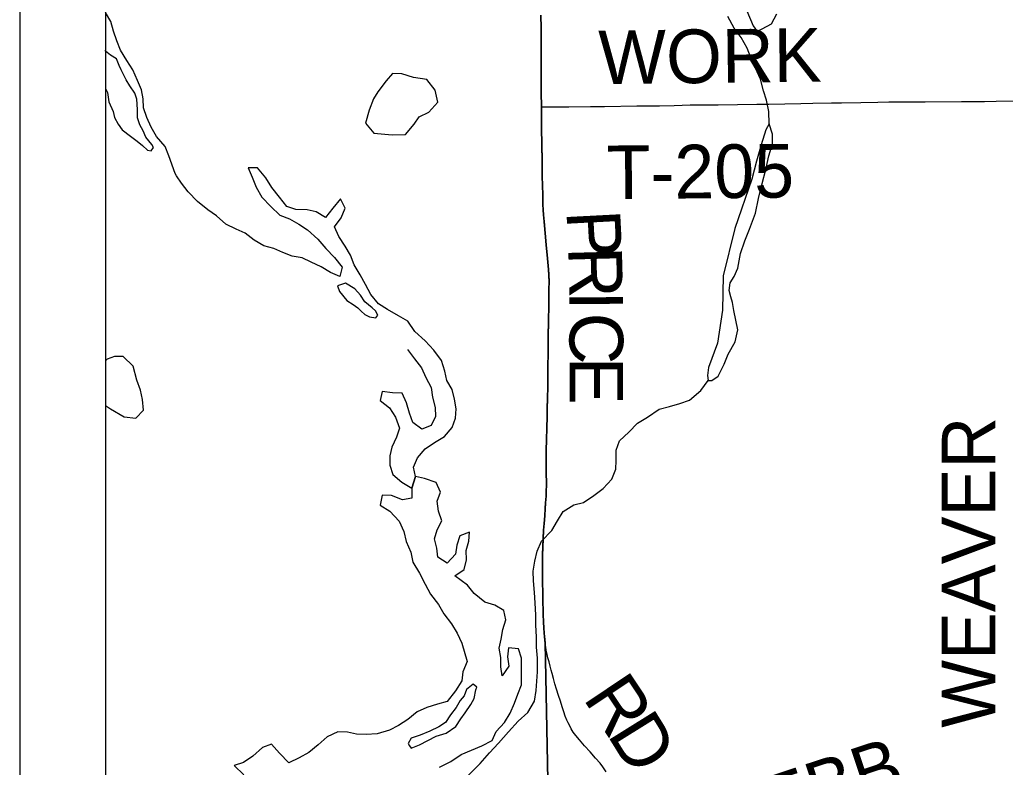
# Model space of a CAD drawing. Extents: x 0 to 34, y 0 to 22.
# Drawn here: x 12.556 to 13.6, y 13.505 to 14.297 of the extents above; entities that cross this region are included whole.
import ezdxf

# ---------------------------------------------------------------- set-up
doc = ezdxf.new("R2010")
doc.units = 0
for name, color, linetype in [('GM_X_Corporation', 7, 'Continuous'), ('GM_X_County_Road_Text', 7, 'Continuous'), ('GM_X_Major_Lake', 7, 'Continuous'), ('GM_X_Major_River', 7, 'Continuous'), ('GM_X_Minor_Lake', 7, 'Continuous'), ('GM_X_Minor_River', 7, 'Continuous'), ('GM_X_Township_Road', 7, 'Continuous'), ('GM_X_Township_Road_Text', 7, 'Continuous'), ('SH_Data', 7, 'Continuous')]:
    doc.layers.add(name, color=color, linetype=linetype)

msp = doc.modelspace()

# ---------------------------------------------------------------- linework, layer by layer
at = {"layer": 'GM_X_Corporation'}
for points in [[(12.6467, 16.7214), (12.6467, 12.6578)], [(12.6467, 16.7214), (12.6467, 12.6578)], [(13.1224, 13.1277), (13.1125, 13.6369), (13.1121, 13.6402), (13.1118, 13.6437), (13.1116, 13.6469), (13.1112, 13.6528), (13.1109, 13.6587), (13.1105, 13.6672), (13.1104, 13.6719), (13.1102, 13.6796), (13.1101, 13.686), (13.11, 13.6925), (13.1099, 13.6984), (13.1098, 13.7049), (13.1099, 13.7101), (13.1099, 13.7182), (13.1099, 13.73), (13.1102, 13.7387), (13.1106, 13.7476), (13.111, 13.756), (13.1115, 13.7632), (13.1121, 13.7714), (13.1127, 13.7791), (13.1131, 13.7852), (13.1136, 13.7923), (13.1138, 13.7982), (13.1139, 13.803), (13.1139, 13.8088), (13.1138, 13.814), (13.1137, 13.8196), (13.1136, 13.8235), (13.1136, 13.8295), (13.1136, 13.8333), (13.1137, 13.8414), (13.114, 13.8512), (13.1144, 13.8651), (13.1146, 13.8754), (13.1148, 13.885), (13.1151, 13.8963), (13.1153, 13.9075), (13.1155, 13.9187), (13.1156, 13.929), (13.1157, 13.944), (13.1158, 13.958), (13.1162, 13.9811), (13.1164, 13.9909), (13.1166, 14.0047), (13.1166, 14.0115), (13.1167, 14.0191), (13.1164, 14.0268), (13.1161, 14.0323), (13.1151, 14.0439), (13.1138, 14.0585), (13.1114, 14.0829), (13.1109, 14.0901), (13.1105, 14.0954), (13.1103, 14.101), (13.11, 14.1119), (13.1098, 14.1203), (13.1095, 14.1318), (13.1093, 14.1464), (13.109, 14.1658), (13.1089, 14.1808), (13.1087, 14.2049), (13.1085, 14.2194), (13.1084, 14.2355), (13.1083, 14.2594), (13.1083, 14.2707), (13.1082, 14.2879), (13.1081, 14.3017)], [(13.1224, 13.1277), (13.1125, 13.6369), (13.1121, 13.6402), (13.1118, 13.6437), (13.1116, 13.6469), (13.1112, 13.6528), (13.1109, 13.6587), (13.1105, 13.6672), (13.1104, 13.6719), (13.1102, 13.6796), (13.1101, 13.686), (13.11, 13.6925), (13.1099, 13.6984), (13.1098, 13.7049), (13.1099, 13.7101), (13.1099, 13.7182), (13.1099, 13.73), (13.1102, 13.7387), (13.1106, 13.7476), (13.111, 13.756), (13.1115, 13.7632), (13.1121, 13.7714), (13.1127, 13.7791), (13.1131, 13.7852), (13.1136, 13.7923), (13.1138, 13.7982), (13.1139, 13.803), (13.1139, 13.8088), (13.1138, 13.814), (13.1137, 13.8196), (13.1136, 13.8235), (13.1136, 13.8295), (13.1136, 13.8333), (13.1137, 13.8414), (13.114, 13.8512), (13.1144, 13.8651), (13.1146, 13.8754), (13.1148, 13.885), (13.1151, 13.8963), (13.1153, 13.9075), (13.1155, 13.9187), (13.1156, 13.929), (13.1157, 13.944), (13.1158, 13.958), (13.1162, 13.9811), (13.1164, 13.9909), (13.1166, 14.0047), (13.1166, 14.0115), (13.1167, 14.0191), (13.1164, 14.0268), (13.1161, 14.0323), (13.1151, 14.0439), (13.1138, 14.0585), (13.1114, 14.0829), (13.1109, 14.0901), (13.1105, 14.0954), (13.1103, 14.101), (13.11, 14.1119), (13.1098, 14.1203), (13.1095, 14.1318), (13.1093, 14.1464), (13.109, 14.1658), (13.1089, 14.1808), (13.1087, 14.2049), (13.1085, 14.2194), (13.1084, 14.2355), (13.1083, 14.2594), (13.1083, 14.2707), (13.1082, 14.2879), (13.1081, 14.3017)], [(13.1081, 14.3017), (13.1082, 14.2879), (13.1083, 14.2707), (13.1083, 14.2594), (13.1084, 14.2355), (13.1085, 14.2194), (13.1087, 14.2049), (13.1089, 14.1808), (13.109, 14.1658), (13.1093, 14.1464), (13.1095, 14.1318), (13.1098, 14.1203), (13.11, 14.1119), (13.1103, 14.101), (13.1105, 14.0954), (13.1109, 14.0901), (13.1114, 14.0829), (13.1138, 14.0585), (13.1151, 14.0439), (13.1161, 14.0323), (13.1164, 14.0268), (13.1167, 14.0191), (13.1166, 14.0115), (13.1166, 14.0047), (13.1164, 13.9909), (13.1162, 13.9811), (13.1158, 13.958), (13.1157, 13.944), (13.1156, 13.929), (13.1155, 13.9187), (13.1153, 13.9075), (13.1151, 13.8963), (13.1148, 13.885), (13.1146, 13.8754), (13.1144, 13.8651), (13.114, 13.8512), (13.1137, 13.8414), (13.1136, 13.8333), (13.1136, 13.8295), (13.1136, 13.8235), (13.1137, 13.8196), (13.1138, 13.814), (13.1139, 13.8088), (13.1139, 13.803), (13.1138, 13.7982), (13.1136, 13.7923), (13.1131, 13.7852), (13.1127, 13.7791), (13.1121, 13.7714), (13.1115, 13.7632), (13.111, 13.756), (13.1106, 13.7476), (13.1102, 13.7387), (13.1099, 13.73), (13.1099, 13.7182), (13.1099, 13.7101), (13.1098, 13.7049), (13.1099, 13.6984), (13.11, 13.6925), (13.1101, 13.686), (13.1102, 13.6796), (13.1104, 13.6719), (13.1105, 13.6672), (13.1109, 13.6587), (13.1112, 13.6528), (13.1116, 13.6469), (13.1118, 13.6437), (13.1121, 13.6402), (13.1125, 13.6369), (13.1224, 13.1277)]]:
    msp.add_lwpolyline(points, dxfattribs=at)
at = {"layer": 'GM_X_Major_Lake'}
for p, q in [((12.9752, 13.813), (12.9713, 13.8008)), ((12.9752, 13.813), (12.9713, 13.8008)), ((13.0185, 13.5683), (13.0122, 13.5606))]:
    msp.add_line(p, q, dxfattribs=at)
for points in [[(13.0304, 13.6979), (13.0169, 13.7076), (13.0267, 13.7145), (13.0293, 13.7248), (13.0291, 13.7347), (13.0317, 13.7446), (13.0323, 13.7541), (13.0222, 13.7502), (13.0189, 13.7403), (13.0178, 13.7308), (13.0088, 13.7212), (12.9989, 13.7275), (12.9977, 13.737), (12.9953, 13.7468), (12.9982, 13.7564), (13.003, 13.7659), (12.9995, 13.7761), (12.9983, 13.7867), (13.0016, 13.7963), (12.9973, 13.8068), (12.9847, 13.8109), (12.9752, 13.813)], [(12.9713, 13.8008), (12.9714, 13.7902), (12.9616, 13.7882), (12.9498, 13.793), (12.94, 13.7933), (12.9378, 13.7827), (12.948, 13.7763), (12.958, 13.7658), (12.963, 13.7548), (12.9653, 13.7442), (12.9703, 13.7329)], [(12.9703, 13.7329), (12.9723, 13.7223), (12.9796, 13.7106), (12.9854, 13.6989), (12.9911, 13.6883), (12.9995, 13.6773), (13.0053, 13.6675), (13.0133, 13.657), (13.0194, 13.6472), (13.0244, 13.6366), (13.0299, 13.6169), (13.0254, 13.6062), (13.0244, 13.5964), (13.0176, 13.5861), (13.0087, 13.5746), (12.9985, 13.5719), (12.9871, 13.5684), (12.9769, 13.5638), (12.9672, 13.5557), (12.9574, 13.5492), (12.9476, 13.5442), (12.9347, 13.5403), (12.923, 13.5398), (12.9128, 13.5401), (12.9033, 13.5423), (12.8931, 13.5426), (12.8818, 13.5372), (12.872, 13.5288), (12.8622, 13.5208), (12.8521, 13.515), (12.8411, 13.5096), (12.8312, 13.5198), (12.8228, 13.5296), (12.813, 13.5261), (12.8028, 13.5169), (12.7931, 13.51), (12.7832, 13.5069), (12.7935, 13.4971)], [(13.0006, 13.505), (13.0126, 13.5112), (13.0235, 13.5186), (13.0345, 13.5233), (13.0454, 13.5276), (13.0563, 13.5334), (13.0608, 13.5429), (13.0694, 13.5525), (13.0757, 13.5625), (13.0801, 13.5728), (13.0838, 13.5823), (13.0875, 13.5922), (13.0877, 13.6017), (13.0875, 13.6207), (13.0844, 13.6306), (13.0738, 13.6316), (13.0727, 13.6221), (13.074, 13.6122), (13.0669, 13.6019), (13.0657, 13.6113), (13.0656, 13.6212), (13.0639, 13.6311), (13.0661, 13.6406), (13.0679, 13.6509), (13.0708, 13.6612), (13.0688, 13.671), (13.0593, 13.6766), (13.0486, 13.6799), (13.0375, 13.6889), (13.0304, 13.6979)], [(13.0122, 13.5606), (13.0069, 13.5526), (12.9998, 13.548), (12.9903, 13.5434), (12.9802, 13.5391), (12.9707, 13.536), (12.9674, 13.5303), (12.9689, 13.5277), (12.9708, 13.5254), (12.9795, 13.5289), (12.9972, 13.5381), (13.0078, 13.5412), (13.0179, 13.5482), (13.0232, 13.5565), (13.0277, 13.5626), (13.034, 13.5714), (13.0374, 13.5779), (13.0392, 13.587), (13.0403, 13.5897), (13.0365, 13.5931), (13.0294, 13.5873), (13.0268, 13.5808), (13.0226, 13.5759), (13.0185, 13.5683)]]:
    msp.add_lwpolyline(points, dxfattribs=at)
at = {"layer": 'GM_X_Major_River'}
for p, q in [((12.6467, 14.2239), (12.649, 14.2197)), ((12.9024, 13.9994), (12.9093, 13.9953)), ((12.9713, 13.8008), (12.9752, 13.813)), ((12.9713, 13.8008), (12.9752, 13.813))]:
    msp.add_line(p, q, dxfattribs=at)
for points in [[(12.7207, 14.1339), (12.7139, 14.1527), (12.71, 14.1625), (12.7009, 14.173), (12.6951, 14.1829), (12.6905, 14.1931), (12.687, 14.2033), (12.6869, 14.2128), (12.685, 14.2226), (12.6807, 14.2324), (12.6757, 14.2438), (12.6696, 14.2536), (12.6627, 14.2645), (12.6588, 14.2744), (12.6554, 14.2846), (12.6526, 14.2948), (12.6467, 14.3045)], [(12.649, 14.2197), (12.6503, 14.2098), (12.6549, 14.1996), (12.6564, 14.1932), (12.6603, 14.186), (12.6645, 14.18), (12.6732, 14.1736), (12.6805, 14.1683), (12.6862, 14.1634), (12.6912, 14.1586), (12.6953, 14.1578), (12.6976, 14.1613), (12.696, 14.1647), (12.6895, 14.1722), (12.6868, 14.179), (12.6834, 14.1854), (12.6807, 14.193), (12.6806, 14.2017), (12.6801, 14.2127), (12.6778, 14.2188), (12.6728, 14.2267), (12.6686, 14.2331), (12.6636, 14.2437), (12.6613, 14.2482), (12.6586, 14.2554), (12.6522, 14.2591), (12.6468, 14.2633), (12.6467, 14.2644)], [(12.9752, 13.813), (12.9732, 13.8229), (12.9773, 13.8328), (12.9855, 13.8424), (12.9953, 13.849), (13.0058, 13.8552), (13.0141, 13.8648), (13.0177, 13.8747), (13.0184, 13.8846), (13.0164, 13.8948), (13.014, 13.905), (13.0086, 13.9148), (13.0062, 13.9247), (13.0027, 13.936), (12.9946, 13.9469), (12.9854, 13.9567), (12.9747, 13.9665), (12.9673, 13.9774), (12.9571, 13.9833), (12.9456, 13.9897), (12.9361, 13.996), (12.928, 14.0058), (12.9222, 14.0163), (12.9168, 14.0265), (12.9103, 14.0371), (12.9064, 14.0473), (12.9006, 14.0571), (12.894, 14.0673), (12.8894, 14.0775), (12.8964, 14.0871), (12.9009, 14.097), (12.8958, 14.1072), (12.8876, 14.0972), (12.8798, 14.0872), (12.8699, 14.0932), (12.8604, 14.0954), (12.8486, 14.0956), (12.8391, 14.0989), (12.8311, 14.1087), (12.823, 14.1192), (12.8168, 14.1294), (12.808, 14.1399), (12.7981, 14.1398), (12.8024, 14.13), (12.8063, 14.1194), (12.8125, 14.1089), (12.8221, 14.0991), (12.8317, 14.0897), (12.8419, 14.0857), (12.8515, 14.0801), (12.861, 14.0741), (12.8717, 14.0644), (12.8801, 14.0546), (12.8893, 14.0448), (12.8974, 14.0347), (12.8952, 14.0248), (12.8853, 14.0292), (12.8754, 14.0352), (12.8648, 14.04), (12.8553, 14.0444), (12.8446, 14.0462), (12.8347, 14.0503), (12.8252, 14.0543), (12.8146, 14.0572), (12.8043, 14.0632), (12.7948, 14.0707), (12.7852, 14.0751), (12.7742, 14.0803), (12.7646, 14.0889), (12.7551, 14.0953), (12.7444, 14.1043), (12.7344, 14.1144), (12.7272, 14.1237), (12.7221, 14.1313), (12.7207, 14.1339)], [(12.9093, 13.9953), (12.9142, 13.9915), (12.9176, 13.9881), (12.9215, 13.9847), (12.9264, 13.9821), (12.9332, 13.981), (12.9355, 13.9837), (12.9328, 13.9886), (12.9294, 13.9916), (12.9217, 13.998), (12.9171, 14.0052), (12.911, 14.0116), (12.9011, 14.0176), (12.8925, 14.0148), (12.8948, 14.0088), (12.9024, 13.9994)], [(12.9668, 13.9475), (12.9741, 13.9377), (12.9817, 13.9279), (12.9863, 13.9177), (12.9917, 13.9071), (12.9933, 13.8969), (12.996, 13.8859), (12.9965, 13.8765), (12.992, 13.8669), (12.9818, 13.8631), (12.9723, 13.8702), (12.9688, 13.88), (12.9657, 13.891), (12.9611, 13.9012), (12.9509, 13.9015), (12.9399, 13.9029), (12.9377, 13.8934), (12.9476, 13.8856), (12.9541, 13.8757), (12.9583, 13.864), (12.955, 13.8545), (12.9502, 13.8442), (12.948, 13.8347), (12.9481, 13.8249), (12.9512, 13.815), (12.9607, 13.8071), (12.9713, 13.8008)]]:
    msp.add_lwpolyline(points, dxfattribs=at)
at = {"layer": 'GM_X_Minor_Lake'}
for p, q in [((12.9441, 14.2322), (12.9355, 14.2204)), ((13.3314, 14.1279), (13.3136, 14.0758)), ((12.6486, 13.9371), (12.6467, 13.9354))]:
    msp.add_line(p, q, dxfattribs=at)
for points in [[(13.3262, 14.3061), (13.3331, 14.2902), (13.3373, 14.2842), (13.3524, 14.2923), (13.358, 14.3029)], [(12.9355, 14.2204), (12.9307, 14.2131), (12.9262, 14.201), (12.9222, 14.1873), (12.931, 14.1767), (12.9506, 14.175), (12.9646, 14.1751), (12.974, 14.1862), (12.9793, 14.1938), (12.9894, 14.1988), (12.9988, 14.2095), (12.9961, 14.222), (12.9873, 14.2333), (12.9733, 14.2355), (12.9607, 14.2395), (12.9509, 14.2398), (12.9441, 14.2322)], [(13.3136, 14.0758), (13.3011, 14.0256), (13.3006, 13.9892), (13.2952, 13.9542), (13.2856, 13.9284), (13.2845, 13.92), (13.2853, 13.9147), (13.2891, 13.9147), (13.2959, 13.9193), (13.3022, 13.9319), (13.3063, 13.9426), (13.3138, 13.9555), (13.3167, 13.9684), (13.3124, 13.9889), (13.3112, 13.9972), (13.3092, 14.0033), (13.3077, 14.0101), (13.3087, 14.0181), (13.3129, 14.0249), (13.3166, 14.0337), (13.3195, 14.0492), (13.3243, 14.0626), (13.3291, 14.0751), (13.3354, 14.0919), (13.3387, 14.1074), (13.342, 14.1219), (13.3468, 14.1397), (13.3497, 14.1527), (13.3534, 14.1652), (13.3533, 14.1754), (13.3498, 14.1864), (13.3465, 14.1803), (13.3413, 14.1643), (13.3365, 14.1469), (13.3314, 14.1279)], [(12.6467, 13.8881), (12.652, 13.8848), (12.6665, 13.8762), (12.679, 13.8747), (12.6872, 13.8832), (12.686, 13.8945), (12.684, 13.9044), (12.6802, 13.915), (12.6763, 13.9297), (12.6656, 13.9399), (12.6565, 13.9402), (12.6486, 13.9371)]]:
    msp.add_lwpolyline(points, dxfattribs=at)
at = {"layer": 'GM_X_Minor_River'}
for points in [[(13.3498, 14.1864), (13.3497, 14.1997), (13.347, 14.2114), (13.3439, 14.2213), (13.3408, 14.2338), (13.3354, 14.2455), (13.3308, 14.2557), (13.3265, 14.2666), (13.3204, 14.278), (13.3127, 14.2878), (13.3062, 14.3002)], [(13.1014, 13.575), (13.1032, 13.5864), (13.1045, 13.6061), (13.1044, 13.6205), (13.1036, 13.6323), (13.1035, 13.6429), (13.1026, 13.6558), (13.1026, 13.666), (13.1021, 13.6793), (13.1012, 13.6903), (13.1004, 13.7024), (13.0999, 13.7126), (13.1017, 13.7233), (13.1043, 13.7339), (13.1088, 13.7446), (13.1197, 13.7557), (13.1256, 13.7659), (13.1316, 13.7758), (13.1429, 13.7828), (13.1531, 13.7855), (13.164, 13.7928), (13.1742, 13.8001), (13.1832, 13.81), (13.1873, 13.8207), (13.188, 13.8301), (13.1879, 13.8408), (13.1912, 13.8506), (13.2013, 13.8598), (13.2104, 13.8694), (13.2209, 13.8759), (13.2333, 13.8844), (13.2443, 13.8871), (13.2552, 13.8902), (13.2654, 13.8937), (13.2775, 13.904), (13.2853, 13.9147)], [(13.0312, 13.4963), (13.0436, 13.5089), (13.0537, 13.5204), (13.0631, 13.5307), (13.0736, 13.5425), (13.0841, 13.554), (13.0943, 13.5632), (13.1014, 13.575)]]:
    msp.add_lwpolyline(points, dxfattribs=at)
at = {"layer": 'GM_X_Township_Road'}
for points in [[(13.1089, 14.2044), (13.1087, 14.2189), (13.1086, 14.235), (13.1086, 14.2589), (13.1085, 14.2701), (13.1084, 14.2874), (13.1083, 14.3012)], [(13.1089, 14.2044), (13.1376, 14.2046), (13.1606, 14.2047), (13.1755, 14.2049), (13.2097, 14.2054), (13.2339, 14.2057), (13.2494, 14.206), (13.2662, 14.2065), (13.296, 14.2067), (13.337, 14.2072), (13.3494, 14.2072), (13.3836, 14.208), (13.396, 14.2082), (13.4158, 14.2086), (13.4264, 14.2089), (13.4469, 14.209), (13.4649, 14.2094), (13.4767, 14.2097), (13.4972, 14.2097), (13.5152, 14.2097), (13.5537, 14.21), (13.5779, 14.2102), (13.5903, 14.2104), (13.6128, 14.2108)], [(13.1127, 13.6364), (13.1123, 13.6396), (13.112, 13.6431), (13.1118, 13.6463), (13.1114, 13.6522), (13.1111, 13.6581), (13.1108, 13.6666), (13.1106, 13.6713), (13.1104, 13.6791), (13.1103, 13.6854), (13.1102, 13.6919), (13.1101, 13.6979), (13.11, 13.7044), (13.1101, 13.7095), (13.1101, 13.7176), (13.1102, 13.7294), (13.1104, 13.7381), (13.1108, 13.7471), (13.1112, 13.7554), (13.1117, 13.7626), (13.1123, 13.7708), (13.1129, 13.7786), (13.1133, 13.7846), (13.1138, 13.7917), (13.114, 13.7976), (13.1141, 13.8024), (13.1141, 13.8083), (13.114, 13.8134), (13.1139, 13.8191), (13.1138, 13.8229), (13.1138, 13.829), (13.1138, 13.8328), (13.1139, 13.8409), (13.1142, 13.8506), (13.1146, 13.8646), (13.1148, 13.8749), (13.115, 13.8844), (13.1153, 13.8957), (13.1155, 13.907), (13.1157, 13.9182), (13.1158, 13.9285), (13.1159, 13.9434), (13.116, 13.9575), (13.1164, 13.9805), (13.1166, 13.9904), (13.1168, 14.0041), (13.1168, 14.011), (13.1169, 14.0186), (13.1166, 14.0262), (13.1163, 14.0317), (13.1153, 14.0434), (13.114, 14.0579), (13.1116, 14.0823), (13.1111, 14.0895), (13.1107, 14.0948), (13.1105, 14.1004), (13.1102, 14.1113), (13.11, 14.1198), (13.1097, 14.1313), (13.1095, 14.1458), (13.1092, 14.1653), (13.1091, 14.1802), (13.1089, 14.2044)], [(13.1773, 13.5002), (13.1738, 13.5054), (13.171, 13.5093), (13.166, 13.5148), (13.1603, 13.5212), (13.1542, 13.5279), (13.1489, 13.5342), (13.1452, 13.5386), (13.1424, 13.5423), (13.1403, 13.5458), (13.139, 13.5481), (13.1369, 13.5522), (13.1357, 13.5549), (13.1339, 13.5593), (13.1324, 13.5637), (13.1307, 13.5692), (13.1288, 13.5752), (13.1269, 13.5812), (13.1247, 13.5877), (13.123, 13.5933), (13.1215, 13.5989), (13.12, 13.6043), (13.119, 13.608), (13.118, 13.612), (13.1168, 13.6166), (13.1156, 13.621), (13.1148, 13.6246), (13.1138, 13.6291), (13.1133, 13.6322), (13.113, 13.6343), (13.1127, 13.6364)]]:
    msp.add_lwpolyline(points, dxfattribs=at)
at = {"layer": 'SH_Data'}
msp.add_line((12.556, 16.8098), (12.556, 9.8098), dxfattribs=at)

# ---------------------------------------------------------------- texts
at = {"layer": 'GM_X_County_Road_Text'}
for s, rotation, p in [('WEAVER', 90, (13.5896, 13.5469)), ('WEBB', 18.2856, (13.2841, 13.4139))]:
    msp.add_text(s, height=0.05682, rotation=rotation, dxfattribs=at).set_placement(p)
at = {"layer": 'GM_X_Township_Road_Text'}
for s, height, rotation, p in [('WORK', 0.05682, 0.6735, (13.1693, 14.2284)), ('T-205', 0.05682, 0.5557, (13.178, 14.1066)), ('P', 0.0568, 272.9663, (13.1351, 14.094)), ('R', 0.0568, 271.5457, (13.137, 14.056)), ('I', 0.0568, 270.3279, (13.1383, 14.0097)), ('C', 0.0568, 270.0156, (13.1384, 13.9865)), ('E', 0.0568, 270, (13.1384, 13.9398)), ('R', 0.0568, 303.7702, (13.1519, 13.5783)), ('D', 0.0568, 301.9359, (13.1776, 13.5399))]:
    msp.add_text(s, height=height, rotation=rotation, dxfattribs=at).set_placement(p)

doc.saveas('drawing.dxf')
